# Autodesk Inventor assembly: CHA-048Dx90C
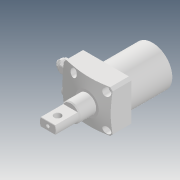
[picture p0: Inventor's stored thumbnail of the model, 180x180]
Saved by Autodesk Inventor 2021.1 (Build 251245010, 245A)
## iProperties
Created: 2019-12
Part Number: CHA-048Dx90C
Description: STEP AP203
Document SubType Name: Assembly
Designer: user
Title: CHA-048Dx90C.STEP
Revision Number: ÈÎºÎ
Sending System: SolidWorks 2017
Preprocessor: SwSTEP 2.0
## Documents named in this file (5)
- D:\Vault_2016\Projekty\Clamptek\Hydraulic\CHA\CHA\CHA-048\Inventor\CHA-048Dx90C\CHA-048Dx90C.iam
- D:\Vault_2016\Projekty\Clamptek\Hydraulic\CHA\CHA\CHA-048\Inventor\CHA-048Dx90C\CHA-048±¾Ìå.ipt
- D:\Vault_2016\Projekty\Clamptek\Hydraulic\CHA\CHA\CHA-048\Inventor\CHA-048Dx90C\CHA-048D(Ë«±Û£©»îÈû¸Ë.ipt
- D:\Vault_2016\Projekty\Clamptek\Hydraulic\CHA\CHA\CHA-048\Inventor\CHA-048Dx90C\G1-8¶ÂÍ·.ipt
- D:\Vault_2016\Projekty\Clamptek\Hydraulic\CHA\CHA\CHA-048\Inventor\CHA-048Dx90C\CZL10µ÷ËÙ·§.ipt
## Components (4 placed, 4 different names)
1. CHA-048±¾Ìå_1
2. CHA-048D(Ë«±Û£©»îÈû¸Ë_2
3. G1-8¶ÂÍ·_3
4. CZL10µ÷ËÙ·§_4
